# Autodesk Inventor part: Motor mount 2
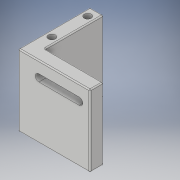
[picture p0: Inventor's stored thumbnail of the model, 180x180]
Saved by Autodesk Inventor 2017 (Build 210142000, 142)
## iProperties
Created: 2016-10
Part Number: Motor mount 2
Material: Generic
Document SubType Name: Modeling
Designer: Stan
Density: 1 g/cm^3
Appearance: Default
Author: Stan
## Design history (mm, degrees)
sketch "Sketch1"
  geometry: L1 (9.525, -34.925)-(9.525, -76.2); L2 (9.525, -76.2)-(19.05, -76.2); L3 (19.05, -76.2)-(19.05, -25.4); L4 (19.05, -25.4)-(-31.75, -25.4); L5 (-31.75, -25.4)-(-31.75, -34.925); L6 (-31.75, -34.925)-(9.525, -34.925); 1 further point
  constraints: 12 end point, 3 perpendicular, 1 parallel
  dimensions: "d3" = 9.525 distance between parallel lines of L1 L3; "d5" = 50.8 distance of L3.end L4.end; "d6" = 9.525 distance of L4.end L5.end; "d9" = 50.8 distance between parallel lines of L4 L2
extrude "Extrusion1" new body sketch "Sketch1" distance "d7" = 50.8; taper "d8" = 0 deg
sketch "Sketch2"
  geometry: L1 (50.8, 0)-(0, 0) reference; L2 (14.605, 42.672)-(43.18, 42.672); L3 (43.18, 37.592)-(14.605, 37.592); A1 r 2.54 centre (14.605, 40.132) between (14.605, 42.672) and (14.605, 37.592); A2 r 2.54 centre (43.18, 40.132) between (43.18, 37.592) and (43.18, 42.672); 2 further points
  constraints: 4 end point, 4 point on circle, 2 centre point, 2 tangent, 1 horizontal, 1 parallel
  dimensions: "d10" = 5.08 diameter of A1; "d11" = 5.08 diameter of A2; "d12" = 40.132 distance from line of L1 A2.centre; "d13" = 40.132 distance from line of L1 A1.centre; "d14" = 5.08 horizontal distance of point (9.525, 50.8) A1.centre; "d15" = 28.575 distance of A2.centre A1.centre
extrude "Extrusion2" cut sketch "Sketch2" distance "d16" = 9.525; taper "d17" = 0 deg
fillet "Fillet1" dims "d18" = 0.762
sketch "Sketch3"
  geometry: L1 (-10.287, 76.2)-(-18.288, 76.2) reference; L2 (-9.525, 35.687)-(-9.525, 75.438) reference; C1 r 2.54 at (-14.288, 69.85); C2 r 2.54 at (-14.287, 44.45); 1 further point
  constraints: 2 centre point
  dimensions: "d19" = 5.08 diameter of C1; "d20" = 5.08 diameter of C2; "d21" = 25.4 distance of C2.centre C1.centre; "d22" = 6.35 distance from line of C1.centre L1; "d23" = 4.7625 distance from line of L2 C1.centre; "d24" = 4.7625 distance from line of L2 C2.centre
extrude "Extrusion3" cut sketch "Sketch3" distance "d25" = 50.8; taper "d26" = 0 deg
body "Solid1"
